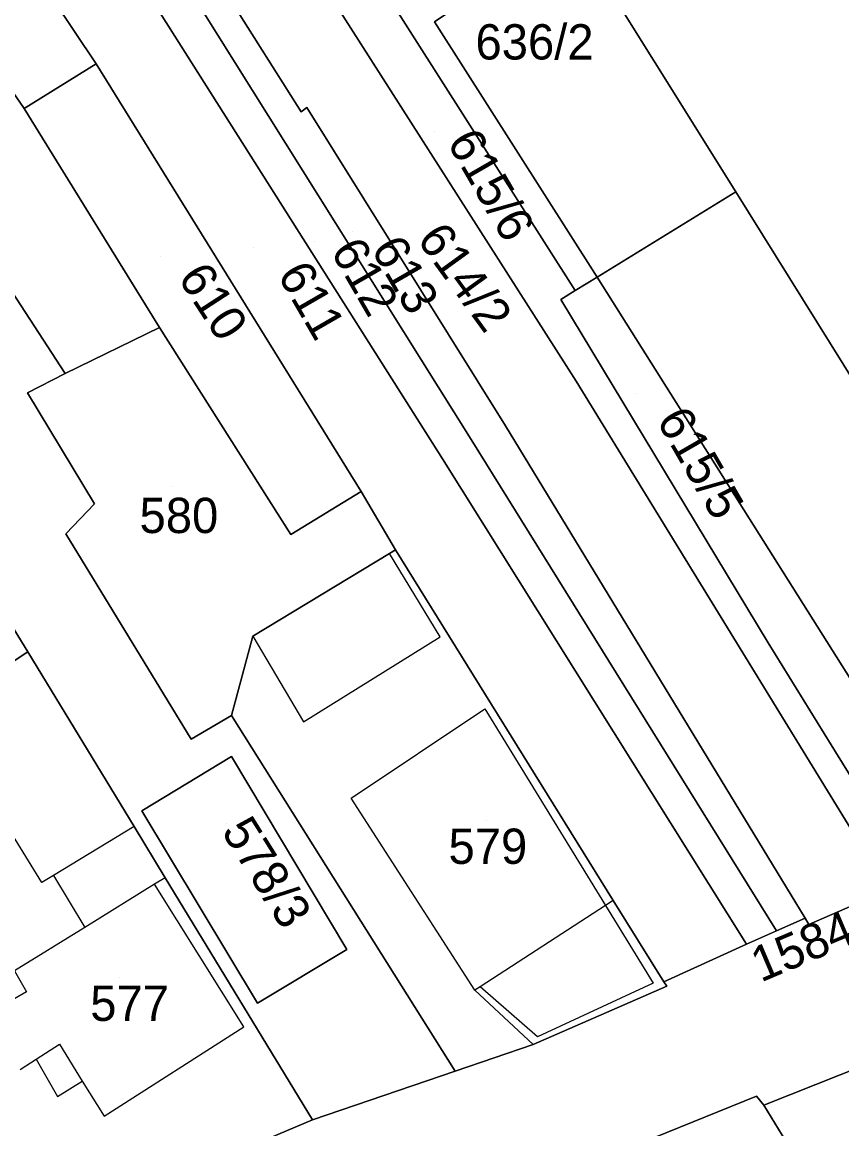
# Model space of a CAD drawing. Extents: x -263943 to -261149, y -1236934 to -1230686.
# Drawn here: x -262582 to -262535.5, y -1235566.3 to -1235503.6 of the extents above; entities that cross this region are included whole.
import ezdxf

# ---------------------------------------------------------------- set-up
doc = ezdxf.new("R2010")
doc.units = 0
for name, color, linetype in [('body_kn', 7, 'Continuous'), ('kladpar_druhypozemkov', 7, 'Continuous'), ('kladpar_hranice', 7, 'Continuous'), ('kladpar_parcelnecisla', 7, 'Continuous'), ('kladpar_plochy', 7, 'Continuous'), ('zappar_hrandruhpozemk', 7, 'Continuous')]:
    doc.layers.add(name, color=color, linetype=linetype)

msp = doc.modelspace()

# ---------------------------------------------------------------- linework, layer by layer
at = {"layer": 'body_kn'}
for p, q in [((-262577.76, -1235505.96), (-262577.76, -1235505.96)), ((-262581.85, -1235508.5), (-262581.85, -1235508.5)), ((-262581.85, -1235508.5), (-262581.85, -1235508.5)), ((-262566.15, -1235508.69), (-262566.15, -1235508.69)), ((-262565.82, -1235508.44), (-262565.82, -1235508.44)), ((-262541.51, -1235513.22), (-262541.51, -1235513.22)), ((-262541.51, -1235513.22), (-262541.51, -1235513.22)), ((-262549.38, -1235518.06), (-262549.38, -1235518.06)), ((-262549.38, -1235518.06), (-262549.38, -1235518.06)), ((-262550.61, -1235518.82), (-262550.61, -1235518.82)), ((-262551.43, -1235519.32), (-262551.43, -1235519.32)), ((-262574.17, -1235520.91), (-262574.17, -1235520.91)), ((-262579.53, -1235523.52), (-262579.53, -1235523.52)), ((-262550.56, -1235523.96), (-262550.56, -1235523.96)), ((-262581.66, -1235524.62), (-262581.66, -1235524.62)), ((-262554.56, -1235526.49), (-262554.56, -1235526.49)), ((-262554.56, -1235526.49), (-262554.56, -1235526.49)), ((-262556.52, -1235527.25), (-262556.52, -1235527.25)), ((-262556.52, -1235527.25), (-262556.52, -1235527.25)), ((-262558.14, -1235528.35), (-262558.14, -1235528.35)), ((-262558.14, -1235528.35), (-262558.14, -1235528.35)), ((-262562.74, -1235530.2), (-262562.74, -1235530.2)), ((-262577.86, -1235530.91), (-262577.86, -1235530.91)), ((-262579.49, -1235532.6), (-262579.49, -1235532.6)), ((-262566.74, -1235532.64), (-262566.74, -1235532.64)), ((-262561.15, -1235533.72), (-262561.15, -1235533.72)), ((-262561.15, -1235533.72), (-262561.15, -1235533.72)), ((-262560.8, -1235533.51), (-262560.8, -1235533.51)), ((-262568.89, -1235538.41), (-262568.89, -1235538.41)), ((-262568.89, -1235538.41), (-262568.89, -1235538.41)), ((-262558.27, -1235538.44), (-262558.27, -1235538.44)), ((-262539.69, -1235538.79), (-262539.69, -1235538.79)), ((-262581.64, -1235539.3), (-262581.64, -1235539.3)), ((-262555.73, -1235542.52), (-262555.73, -1235542.52)), ((-262570.1, -1235542.9), (-262570.1, -1235542.9)), ((-262566.02, -1235543.25), (-262566.02, -1235543.25)), ((-262572.39, -1235544.25), (-262572.39, -1235544.25)), ((-262535.71, -1235545.2), (-262535.71, -1235545.2)), ((-262570.09, -1235545.23), (-262570.09, -1235545.23)), ((-262563.32, -1235547.59), (-262563.32, -1235547.59)), ((-262575.18, -1235548.31), (-262575.18, -1235548.31)), ((-262575.18, -1235548.31), (-262575.18, -1235548.31)), ((-262575.62, -1235549.2), (-262575.62, -1235549.2)), ((-262575.62, -1235549.2), (-262575.62, -1235549.2)), ((-262580.18, -1235551.97), (-262580.18, -1235551.97)), ((-262573.86, -1235552.1), (-262573.86, -1235552.1)), ((-262573.86, -1235552.1), (-262573.86, -1235552.1)), ((-262580.84, -1235552.37), (-262580.84, -1235552.37)), ((-262574.45, -1235552.46), (-262574.45, -1235552.46)), ((-262574.45, -1235552.46), (-262574.45, -1235552.46)), ((-262548.9, -1235553.66), (-262548.9, -1235553.66)), ((-262548.9, -1235553.66), (-262548.9, -1235553.66)), ((-262548.47, -1235553.38), (-262548.47, -1235553.38)), ((-262548.47, -1235553.38), (-262548.47, -1235553.38)), ((-262537.59, -1235554.38), (-262537.59, -1235554.38)), ((-262578.41, -1235554.91), (-262578.41, -1235554.91)), ((-262578.41, -1235554.91), (-262578.41, -1235554.91)), ((-262539.2, -1235555.11), (-262539.2, -1235555.11)), ((-262537.37, -1235554.74), (-262537.37, -1235554.74)), ((-262563.55, -1235556.17), (-262563.55, -1235556.17)), ((-262540.9, -1235555.87), (-262540.9, -1235555.87)), ((-262556, -1235558.27), (-262556, -1235558.27)), ((-262556, -1235558.27), (-262556, -1235558.27)), ((-262546.19, -1235558.08), (-262546.19, -1235558.08)), ((-262545.6, -1235558), (-262545.6, -1235558)), ((-262545.6, -1235558), (-262545.6, -1235558)), ((-262545.43, -1235558.25), (-262545.43, -1235558.25)), ((-262581.71, -1235558.56), (-262581.71, -1235558.56)), ((-262556.31, -1235558.47), (-262556.31, -1235558.47)), ((-262568.62, -1235559.2), (-262568.62, -1235559.2)), ((-262569.4, -1235560.55), (-262569.4, -1235560.55)), ((-262552.75, -1235561.11), (-262552.75, -1235561.11)), ((-262579.85, -1235561.53), (-262579.85, -1235561.53)), ((-262553, -1235561.54), (-262553, -1235561.54)), ((-262553, -1235561.54), (-262553, -1235561.54)), ((-262581.17, -1235562.38), (-262581.17, -1235562.38)), ((-262581.17, -1235562.38), (-262581.17, -1235562.38)), ((-262557.42, -1235563.05), (-262557.42, -1235563.05)), ((-262578.55, -1235563.63), (-262578.55, -1235563.63)), ((-262578.55, -1235563.63), (-262578.55, -1235563.63)), ((-262579.95, -1235564.5), (-262579.95, -1235564.5)), ((-262540.35, -1235564.47), (-262540.35, -1235564.47)), ((-262539.93, -1235564.98), (-262539.93, -1235564.98)), ((-262577.32, -1235565.61), (-262577.32, -1235565.61)), ((-262565.51, -1235565.82), (-262565.51, -1235565.82)), ((-262565.51, -1235565.82), (-262565.51, -1235565.82))]:
    msp.add_line(p, q, dxfattribs=at)
at = {"layer": 'kladpar_druhypozemkov'}
for p, q in [((-262558.57, -1235509.82), (-262558.57, -1235509.82)), ((-262563.23, -1235515.48), (-262563.23, -1235515.48)), ((-262565.38, -1235516.03), (-262565.38, -1235516.03)), ((-262574.13, -1235516.88), (-262574.13, -1235516.88)), ((-262568.83, -1235516.38), (-262568.83, -1235516.38)), ((-262555.9, -1235518.43), (-262555.9, -1235518.43)), ((-262547.12, -1235524.65), (-262547.12, -1235524.65)), ((-262573.49, -1235529.91), (-262573.49, -1235529.91)), ((-262555.64, -1235548.86), (-262555.64, -1235548.86)), ((-262570.39, -1235549.03), (-262570.39, -1235549.03)), ((-262576.44, -1235557.76), (-262576.44, -1235557.76))]:
    msp.add_line(p, q, dxfattribs=at)
at = {"layer": 'kladpar_hranice'}
for points in [[(-262587.55, -1235511.19), (-262589.17, -1235511.95), (-262589.39, -1235511.61), (-262609.32, -1235481.29), (-262623.62, -1235459.84), (-262622.37, -1235459.05), (-262617.61, -1235456.02), (-262617.04, -1235455.65), (-262615.93, -1235457.43), (-262611.93, -1235463.77), (-262603.06, -1235477.63), (-262581.85, -1235508.5), (-262574.17, -1235520.91), (-262579.53, -1235523.52), (-262587.55, -1235511.19)], [(-262528.57, -1235528.58), (-262531.04, -1235530.05), (-262533.15, -1235526.66), (-262541.51, -1235513.22), (-262555.52, -1235490.81), (-262571.48, -1235465.29), (-262556.86, -1235456.18), (-262553.69, -1235462.2), (-262553.35, -1235461.97), (-262553.18, -1235461.86), (-262541.16, -1235481.3), (-262531.67, -1235496), (-262515.62, -1235520.86), (-262528.57, -1235528.58)], [(-262556.52, -1235527.25), (-262591.94, -1235470.73), (-262590.03, -1235469.56), (-262588.67, -1235471.76), (-262579.53, -1235486.44), (-262569.83, -1235502), (-262570.2, -1235502.25), (-262566.15, -1235508.69), (-262565.82, -1235508.44), (-262554.56, -1235526.49), (-262537.59, -1235554.38), (-262539.2, -1235555.11), (-262556.52, -1235527.25)], [(-262558.14, -1235528.35), (-262593.88, -1235471.92), (-262591.94, -1235470.73), (-262556.52, -1235527.25), (-262539.2, -1235555.11), (-262540.9, -1235555.87), (-262558.14, -1235528.35)], [(-262548.47, -1235553.38), (-262560.8, -1235533.51), (-262562.74, -1235530.2), (-262577.76, -1235505.96), (-262598.58, -1235474.91), (-262596.8, -1235473.72), (-262593.88, -1235471.92), (-262558.14, -1235528.35), (-262540.9, -1235555.87), (-262545.6, -1235558), (-262548.47, -1235553.38)], [(-262598.58, -1235474.91), (-262577.76, -1235505.96), (-262581.85, -1235508.5), (-262603.06, -1235477.63), (-262598.58, -1235474.91)], [(-262572.45, -1235481.83), (-262563.71, -1235495.55), (-262562.67, -1235497.18), (-262561.98, -1235496.72), (-262557.77, -1235503.04), (-262558.59, -1235503.59), (-262549.38, -1235518.06), (-262550.61, -1235518.82), (-262573.66, -1235482.62), (-262572.45, -1235481.83)], [(-262533.41, -1235551.91), (-262550.56, -1235523.96), (-262575.97, -1235484.12), (-262573.66, -1235482.62), (-262550.61, -1235518.82), (-262551.43, -1235519.32), (-262539.69, -1235538.79), (-262535.71, -1235545.2), (-262532.05, -1235551.11), (-262533.41, -1235551.91)], [(-262554.56, -1235526.49), (-262565.82, -1235508.44), (-262566.15, -1235508.69), (-262570.2, -1235502.25), (-262569.83, -1235502), (-262579.53, -1235486.44), (-262575.97, -1235484.12), (-262550.56, -1235523.96), (-262533.41, -1235551.91), (-262532.87, -1235552.78), (-262537.37, -1235554.74), (-262537.59, -1235554.38), (-262554.56, -1235526.49)], [(-262563.71, -1235495.55), (-262555.52, -1235490.81), (-262541.51, -1235513.22), (-262549.38, -1235518.06), (-262558.59, -1235503.59), (-262557.77, -1235503.04), (-262561.98, -1235496.72), (-262562.67, -1235497.18), (-262563.71, -1235495.55)], [(-262581.85, -1235508.5), (-262577.76, -1235505.96), (-262562.74, -1235530.2), (-262566.74, -1235532.64), (-262574.17, -1235520.91), (-262581.85, -1235508.5)], [(-262596.25, -1235515.41), (-262589.39, -1235511.61), (-262589.17, -1235511.95), (-262587.55, -1235511.19), (-262579.53, -1235523.52), (-262581.66, -1235524.62), (-262577.86, -1235530.91), (-262579.49, -1235532.6), (-262572.39, -1235544.25), (-262570.1, -1235542.9), (-262557.42, -1235563.05), (-262565.51, -1235565.82), (-262573.86, -1235552.1), (-262575.62, -1235549.2), (-262581.64, -1235539.3), (-262588.98, -1235527.31), (-262596.25, -1235515.41)], [(-262541.51, -1235513.22), (-262533.15, -1235526.66), (-262531.04, -1235530.05), (-262530.83, -1235530.38), (-262526.89, -1235536.56), (-262524.93, -1235539.64), (-262521.94, -1235544.32), (-262520.14, -1235547.14), (-262523.8, -1235548.78), (-262528.46, -1235550.85), (-262529.33, -1235549.49), (-262534.4, -1235541.83), (-262549.38, -1235518.06), (-262541.51, -1235513.22)], [(-262549.38, -1235518.06), (-262534.4, -1235541.83), (-262529.33, -1235549.49), (-262532.05, -1235551.11), (-262535.71, -1235545.2), (-262539.69, -1235538.79), (-262551.43, -1235519.32), (-262550.61, -1235518.82), (-262549.38, -1235518.06)], [(-262561.15, -1235533.72), (-262568.89, -1235538.41), (-262570.1, -1235542.9), (-262572.39, -1235544.25), (-262579.49, -1235532.6), (-262577.86, -1235530.91), (-262581.66, -1235524.62), (-262579.53, -1235523.52), (-262574.17, -1235520.91), (-262566.74, -1235532.64), (-262562.74, -1235530.2), (-262560.8, -1235533.51), (-262561.15, -1235533.72)], [(-262594.76, -1235547.91), (-262597.03, -1235543.99), (-262602.18, -1235535.32), (-262588.98, -1235527.31), (-262581.64, -1235539.3), (-262586.81, -1235542.7), (-262594.76, -1235547.91)], [(-262545.6, -1235558), (-262545.43, -1235558.25), (-262553, -1235561.54), (-262557.42, -1235563.05), (-262570.1, -1235542.9), (-262568.89, -1235538.41), (-262561.15, -1235533.72), (-262560.8, -1235533.51), (-262548.47, -1235553.38), (-262545.6, -1235558)], [(-262580.23, -1235572.05), (-262582.42, -1235568.4), (-262590.74, -1235554.52), (-262591.13, -1235553.86), (-262594.76, -1235547.91), (-262586.81, -1235542.7), (-262581.64, -1235539.3), (-262575.62, -1235549.2), (-262573.86, -1235552.1), (-262565.51, -1235565.82), (-262580.23, -1235572.05)], [(-262575.18, -1235548.31), (-262570.09, -1235545.23), (-262563.55, -1235556.17), (-262568.62, -1235559.2), (-262575.18, -1235548.31)], [(-262570.09, -1235545.23), (-262575.18, -1235548.31), (-262568.62, -1235559.2), (-262563.55, -1235556.17), (-262570.09, -1235545.23)], [(-262565.51, -1235565.82), (-262557.42, -1235563.05), (-262553, -1235561.54), (-262545.43, -1235558.25), (-262545.6, -1235558), (-262540.9, -1235555.87), (-262539.2, -1235555.11), (-262537.59, -1235554.38), (-262537.37, -1235554.74), (-262532.87, -1235552.78)], [(-262532.65, -1235562.1), (-262539.93, -1235564.98), (-262540.35, -1235564.47), (-262546.13, -1235566.81), (-262550.31, -1235568.5), (-262550.6, -1235568.62), (-262559.42, -1235572.29), (-262564.18, -1235574.14), (-262569.31, -1235576.04), (-262578.87, -1235579.57), (-262581.75, -1235580.64), (-262588.52, -1235583.14), (-262593.39, -1235585.64), (-262594.97, -1235586.46), (-262599.16, -1235588.62), (-262609.72, -1235593.27), (-262614.05, -1235595.18), (-262619.84, -1235597.63)], [(-262505.95, -1235610.1), (-262507.84, -1235611.24), (-262510.61, -1235612.92), (-262522.36, -1235593.88), (-262538.27, -1235567.71), (-262539.93, -1235564.98), (-262532.65, -1235562.1), (-262517.49, -1235586.94), (-262513.86, -1235592.89), (-262510.03, -1235590.95), (-262500.23, -1235606.63), (-262502.65, -1235608.1), (-262505.95, -1235610.1)], [(-262529.74, -1235591.31), (-262534.59, -1235594.46), (-262540.33, -1235584.88), (-262548.87, -1235570.63), (-262550.31, -1235568.5), (-262546.13, -1235566.81), (-262540.35, -1235564.47), (-262539.93, -1235564.98), (-262538.27, -1235567.71), (-262522.36, -1235593.88), (-262526.7, -1235596.49), (-262529.74, -1235591.31)], [(-262619.88, -1235589.84), (-262606.53, -1235584.43), (-262603.67, -1235583.21), (-262599.64, -1235581.49), (-262597.74, -1235580.56), (-262592.92, -1235578.2), (-262589.19, -1235576.39), (-262580.23, -1235572.05), (-262565.51, -1235565.82)]]:
    msp.add_lwpolyline(points, dxfattribs=at)
at = {"layer": 'kladpar_plochy'}
for p, q in [((-262587.55, -1235511.19), (-262579.53, -1235523.52)), ((-262579.53, -1235523.52), (-262581.66, -1235524.62)), ((-262581.66, -1235524.62), (-262577.86, -1235530.91)), ((-262581.64, -1235539.3), (-262588.98, -1235527.31)), ((-262577.86, -1235530.91), (-262579.49, -1235532.6)), ((-262579.49, -1235532.6), (-262572.39, -1235544.25)), ((-262575.62, -1235549.2), (-262581.64, -1235539.3)), ((-262572.39, -1235544.25), (-262570.1, -1235542.9)), ((-262570.1, -1235542.9), (-262557.42, -1235563.05)), ((-262570.09, -1235545.23), (-262575.18, -1235548.31)), ((-262563.55, -1235556.17), (-262570.09, -1235545.23)), ((-262575.18, -1235548.31), (-262568.62, -1235559.2)), ((-262573.86, -1235552.1), (-262575.62, -1235549.2)), ((-262565.51, -1235565.82), (-262573.86, -1235552.1)), ((-262568.62, -1235559.2), (-262563.55, -1235556.17)), ((-262557.42, -1235563.05), (-262565.51, -1235565.82))]:
    msp.add_line(p, q, dxfattribs=at)
for points in [[(-262587.55, -1235511.19), (-262589.17, -1235511.95), (-262589.39, -1235511.61), (-262609.32, -1235481.29), (-262623.62, -1235459.84), (-262622.37, -1235459.05), (-262617.61, -1235456.02), (-262617.04, -1235455.65), (-262615.93, -1235457.43), (-262611.93, -1235463.77), (-262603.06, -1235477.63), (-262581.85, -1235508.5), (-262574.17, -1235520.91), (-262579.53, -1235523.52)], [(-262528.57, -1235528.58), (-262531.04, -1235530.05), (-262533.15, -1235526.66), (-262541.51, -1235513.22), (-262555.52, -1235490.81), (-262571.48, -1235465.29), (-262556.86, -1235456.18), (-262553.69, -1235462.2), (-262553.35, -1235461.97), (-262553.18, -1235461.86), (-262541.16, -1235481.3), (-262531.67, -1235496), (-262515.62, -1235520.86)], [(-262556.52, -1235527.25), (-262591.94, -1235470.73), (-262590.03, -1235469.56), (-262588.67, -1235471.76), (-262579.53, -1235486.44), (-262569.83, -1235502), (-262570.2, -1235502.25), (-262566.15, -1235508.69), (-262565.82, -1235508.44), (-262554.56, -1235526.49), (-262537.59, -1235554.38), (-262539.2, -1235555.11)], [(-262558.14, -1235528.35), (-262593.88, -1235471.92), (-262591.94, -1235470.73), (-262556.52, -1235527.25), (-262539.2, -1235555.11), (-262540.9, -1235555.87)], [(-262548.47, -1235553.38), (-262560.8, -1235533.51), (-262562.74, -1235530.2), (-262577.76, -1235505.96), (-262598.58, -1235474.91), (-262596.8, -1235473.72), (-262593.88, -1235471.92), (-262558.14, -1235528.35), (-262540.9, -1235555.87), (-262545.6, -1235558)], [(-262598.58, -1235474.91), (-262577.76, -1235505.96), (-262581.85, -1235508.5), (-262603.06, -1235477.63)], [(-262572.45, -1235481.83), (-262563.71, -1235495.55), (-262562.67, -1235497.18), (-262561.98, -1235496.72), (-262557.77, -1235503.04), (-262558.59, -1235503.59), (-262549.38, -1235518.06), (-262550.61, -1235518.82), (-262573.66, -1235482.62)], [(-262533.41, -1235551.91), (-262550.56, -1235523.96), (-262575.97, -1235484.12), (-262573.66, -1235482.62), (-262550.61, -1235518.82), (-262551.43, -1235519.32), (-262539.69, -1235538.79), (-262535.71, -1235545.2), (-262532.05, -1235551.11)], [(-262554.56, -1235526.49), (-262565.82, -1235508.44), (-262566.15, -1235508.69), (-262570.2, -1235502.25), (-262569.83, -1235502), (-262579.53, -1235486.44), (-262575.97, -1235484.12), (-262550.56, -1235523.96), (-262533.41, -1235551.91), (-262532.87, -1235552.78), (-262537.37, -1235554.74), (-262537.59, -1235554.38)], [(-262563.71, -1235495.55), (-262555.52, -1235490.81), (-262541.51, -1235513.22), (-262549.38, -1235518.06), (-262558.59, -1235503.59), (-262557.77, -1235503.04), (-262561.98, -1235496.72), (-262562.67, -1235497.18)], [(-262581.85, -1235508.5), (-262577.76, -1235505.96), (-262562.74, -1235530.2), (-262566.74, -1235532.64), (-262574.17, -1235520.91)], [(-262541.51, -1235513.22), (-262533.15, -1235526.66), (-262531.04, -1235530.05), (-262530.83, -1235530.38), (-262526.89, -1235536.56), (-262524.93, -1235539.64), (-262521.94, -1235544.32), (-262520.14, -1235547.14), (-262523.8, -1235548.78), (-262528.46, -1235550.85), (-262529.33, -1235549.49), (-262534.4, -1235541.83), (-262549.38, -1235518.06)], [(-262549.38, -1235518.06), (-262534.4, -1235541.83), (-262529.33, -1235549.49), (-262532.05, -1235551.11), (-262535.71, -1235545.2), (-262539.69, -1235538.79), (-262551.43, -1235519.32), (-262550.61, -1235518.82)], [(-262561.15, -1235533.72), (-262568.89, -1235538.41), (-262570.1, -1235542.9), (-262572.39, -1235544.25), (-262579.49, -1235532.6), (-262577.86, -1235530.91), (-262581.66, -1235524.62), (-262579.53, -1235523.52), (-262574.17, -1235520.91), (-262566.74, -1235532.64), (-262562.74, -1235530.2), (-262560.8, -1235533.51)], [(-262594.76, -1235547.91), (-262597.03, -1235543.99), (-262602.18, -1235535.32), (-262588.98, -1235527.31), (-262581.64, -1235539.3), (-262586.81, -1235542.7)], [(-262545.6, -1235558), (-262545.43, -1235558.25), (-262553, -1235561.54), (-262557.42, -1235563.05), (-262570.1, -1235542.9), (-262568.89, -1235538.41), (-262561.15, -1235533.72), (-262560.8, -1235533.51), (-262548.47, -1235553.38)], [(-262580.23, -1235572.05), (-262582.42, -1235568.4), (-262590.74, -1235554.52), (-262591.13, -1235553.86), (-262594.76, -1235547.91), (-262586.81, -1235542.7), (-262581.64, -1235539.3), (-262575.62, -1235549.2), (-262573.86, -1235552.1), (-262565.51, -1235565.82)], [(-262575.18, -1235548.31), (-262570.09, -1235545.23), (-262563.55, -1235556.17), (-262568.62, -1235559.2)], [(-262505.95, -1235610.1), (-262507.84, -1235611.24), (-262510.61, -1235612.92), (-262522.36, -1235593.88), (-262538.27, -1235567.71), (-262539.93, -1235564.98), (-262532.65, -1235562.1), (-262517.49, -1235586.94), (-262513.86, -1235592.89), (-262510.03, -1235590.95), (-262500.23, -1235606.63), (-262502.65, -1235608.1)], [(-262529.74, -1235591.31), (-262534.59, -1235594.46), (-262540.33, -1235584.88), (-262548.87, -1235570.63), (-262550.31, -1235568.5), (-262546.13, -1235566.81), (-262540.35, -1235564.47), (-262539.93, -1235564.98), (-262538.27, -1235567.71), (-262522.36, -1235593.88), (-262526.7, -1235596.49)]]:
    msp.add_lwpolyline(points, close=True, dxfattribs=at)
for points in [[(-262619.88, -1235589.84), (-262606.53, -1235584.43), (-262603.67, -1235583.21), (-262599.64, -1235581.49), (-262597.74, -1235580.56), (-262592.92, -1235578.2), (-262589.19, -1235576.39), (-262580.23, -1235572.05), (-262565.51, -1235565.82), (-262557.42, -1235563.05), (-262553, -1235561.54), (-262545.43, -1235558.25), (-262545.6, -1235558), (-262540.9, -1235555.87), (-262539.2, -1235555.11), (-262537.59, -1235554.38), (-262537.37, -1235554.74), (-262532.87, -1235552.78)], [(-262532.65, -1235562.1), (-262539.93, -1235564.98), (-262540.35, -1235564.47), (-262546.13, -1235566.81), (-262550.31, -1235568.5), (-262550.6, -1235568.62), (-262559.42, -1235572.29), (-262564.18, -1235574.14), (-262569.31, -1235576.04), (-262578.87, -1235579.57), (-262581.75, -1235580.64), (-262588.52, -1235583.14), (-262593.39, -1235585.64), (-262594.97, -1235586.46), (-262599.16, -1235588.62), (-262609.72, -1235593.27), (-262614.05, -1235595.18), (-262619.84, -1235597.63)]]:
    msp.add_lwpolyline(points, dxfattribs=at)
at = {"layer": 'zappar_hrandruhpozemk'}
for p, q in [((-262558.27, -1235538.44), (-262561.15, -1235533.72)), ((-262568.89, -1235538.41), (-262566.02, -1235543.25)), ((-262566.02, -1235543.25), (-262558.27, -1235538.44)), ((-262563.32, -1235547.59), (-262555.73, -1235542.52)), ((-262575.62, -1235549.2), (-262580.18, -1235551.97)), ((-262580.18, -1235551.97), (-262578.41, -1235554.91)), ((-262573.86, -1235552.1), (-262574.45, -1235552.46)), ((-262574.45, -1235552.46), (-262578.41, -1235554.91)), ((-262569.4, -1235560.55), (-262574.45, -1235552.46)), ((-262548.9, -1235553.66), (-262556, -1235558.27)), ((-262548.47, -1235553.38), (-262548.9, -1235553.66)), ((-262556, -1235558.27), (-262556.31, -1235558.47)), ((-262552.75, -1235561.11), (-262556, -1235558.27)), ((-262546.19, -1235558.08), (-262552.75, -1235561.11)), ((-262577.32, -1235565.61), (-262569.4, -1235560.55)), ((-262579.85, -1235561.53), (-262578.55, -1235563.63)), ((-262578.55, -1235563.63), (-262577.32, -1235565.61))]:
    msp.add_line(p, q, dxfattribs=at)
for points in [[(-262555.73, -1235542.52), (-262548.9, -1235553.66), (-262546.19, -1235558.08)], [(-262580.18, -1235551.97), (-262580.84, -1235552.37), (-262586.81, -1235542.7)], [(-262553, -1235561.54), (-262556.31, -1235558.47), (-262563.32, -1235547.59)], [(-262578.41, -1235554.91), (-262582.39, -1235557.37), (-262581.71, -1235558.56), (-262583.93, -1235559.82)], [(-262582.07, -1235562.97), (-262581.17, -1235562.38), (-262579.85, -1235561.53)], [(-262581.17, -1235562.38), (-262579.95, -1235564.5), (-262578.55, -1235563.63)]]:
    msp.add_lwpolyline(points, dxfattribs=at)

# ---------------------------------------------------------------- texts
at = {"layer": 'kladpar_parcelnecisla'}
for s, p in [('636/2', (-262556.268, -1235505.72)), ('580', (-262575.307, -1235532.56)), ('579', (-262557.797, -1235551.31)), ('577', (-262578.1, -1235560.21))]:
    msp.add_text(s, height=2, dxfattribs=at).set_placement(p)
for s, rotation, p in [('615/6', 300, (-262557.918, -1235510.409)), ('614/2', 306, (-262559.633, -1235515.921)), ('612', 300, (-262564.514, -1235516.579)), ('613', 300, (-262562.222, -1235516.465)), ('610', 303, (-262573.175, -1235518.094)), ('611', 300, (-262567.526, -1235517.918)), ('615/5', 300, (-262546.046, -1235526.171)), ('578/3', 302, (-262570.704, -1235549.464)), ('1584/11', 23, (-262540.099, -1235558.046))]:
    msp.add_text(s, height=2, rotation=rotation, dxfattribs=at).set_placement(p)

doc.saveas('drawing.dxf')
